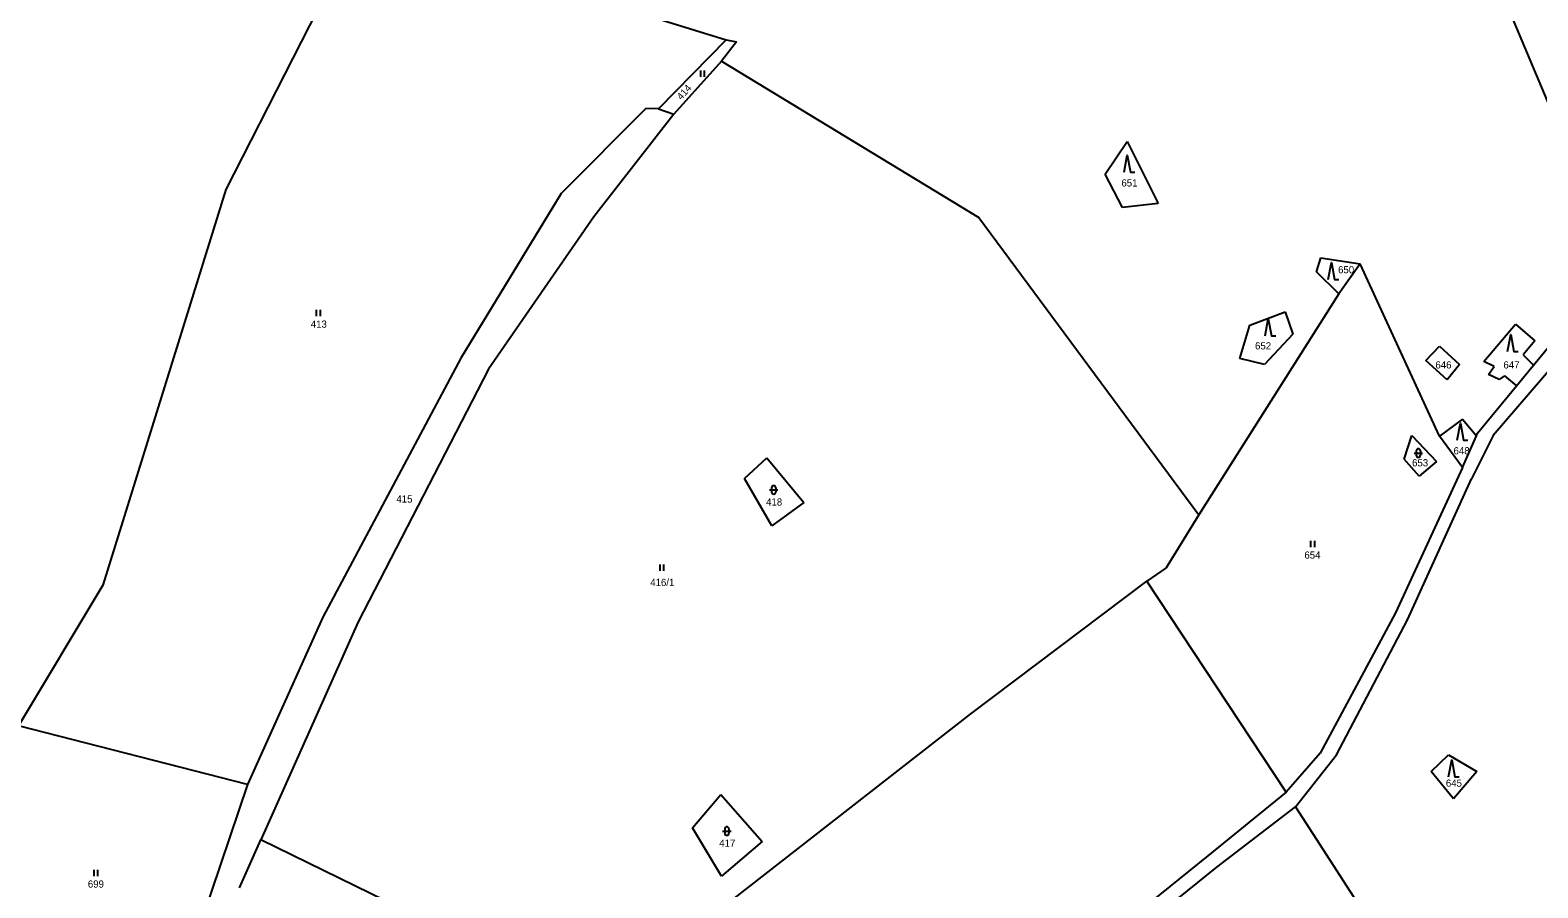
# Model space of a CAD drawing. Extents: x -670359 to -668019, y -978807 to -976674.
# Drawn here: x -668641.1 to -668285.6, y -977601.7 to -977399.4 of the extents above; entities that cross this region are included whole.
import ezdxf

# ---------------------------------------------------------------- set-up
doc = ezdxf.new("R2010")
doc.units = 0
for name, color, linetype in [('Hranice parcel', 7, 'Continuous'), ('Parcelní čísla', 7, 'Continuous'), ('Značky kultur', 7, 'Continuous')]:
    doc.layers.add(name, color=color, linetype=linetype)

msp = doc.modelspace()

# ---------------------------------------------------------------- linework, layer by layer
at = {"layer": 'Hranice parcel'}
msp.add_line((-668557.18, -977604.87), (-668586.71, -977590.44), dxfattribs=at)
for points in [[(-668280.24, -977423.45), (-668302.7, -977370)], [(-668563.4, -977375), (-668594.98, -977437.03)], [(-668563.4, -977375), (-668476.97, -977401.73)], [(-668476.97, -977401.73), (-668493, -977417.97)], [(-668476.97, -977401.73), (-668474.59, -977402.21)], [(-668474.59, -977402.21), (-668478.11, -977406.73)], [(-668478.11, -977406.73), (-668489.36, -977419.22)], [(-668478.11, -977406.73), (-668417.42, -977443.6)], [(-668495.96, -977417.94), (-668515.89, -977437.97)], [(-668489.36, -977419.22), (-668508.24, -977443.44)], [(-668493, -977417.97), (-668495.96, -977417.94)], [(-668493, -977417.97), (-668489.36, -977419.22)], [(-668387.59, -977433.44), (-668382.43, -977425.7)], [(-668382.43, -977425.7), (-668375.1, -977440.36)], [(-668383.54, -977441.27), (-668387.59, -977433.44)], [(-668594.98, -977437.03), (-668623.98, -977530.37)], [(-668515.89, -977437.97), (-668539.61, -977476.83)], [(-668375.1, -977440.36), (-668383.54, -977441.27)], [(-668508.24, -977443.44), (-668533.05, -977479.38)], [(-668417.42, -977443.6), (-668365.52, -977513.77)], [(-668337.79, -977456.48), (-668336.79, -977453.15)], [(-668336.79, -977453.15), (-668327.47, -977454.52)], [(-668327.47, -977454.52), (-668332.52, -977461.63)], [(-668308.8, -977495.19), (-668327.47, -977454.52)], [(-668332.52, -977461.63), (-668337.79, -977456.48)], [(-668332.52, -977461.63), (-668365.52, -977513.77)], [(-668353.53, -977469.05), (-668345.17, -977465.9)], [(-668345.17, -977465.9), (-668343.35, -977471.17)], [(-668269.51, -977464.09), (-668296.09, -977495.03)], [(-668286.58, -977478.47), (-668276.22, -977465.88)], [(-668355.89, -977476.89), (-668353.53, -977469.05)], [(-668298.33, -977477.63), (-668290.89, -977468.77)], [(-668290.89, -977468.77), (-668286.3, -977472.7)], [(-668343.35, -977471.17), (-668350.09, -977478.3)], [(-668286.3, -977472.7), (-668289.07, -977476.04)], [(-668312.02, -977477.39), (-668308.77, -977473.99)], [(-668308.77, -977473.99), (-668304.04, -977478.31)], [(-668289.07, -977476.04), (-668286.58, -977478.47)], [(-668539.61, -977476.83), (-668572.11, -977537.87)], [(-668533.05, -977479.38), (-668563.82, -977538.97)], [(-668350.09, -977478.3), (-668355.89, -977476.89)], [(-668306.97, -977481.89), (-668312.02, -977477.39)], [(-668304.04, -977478.31), (-668306.97, -977481.89)], [(-668295.9, -977478.81), (-668298.33, -977477.63)], [(-668297.2, -977480.68), (-668295.9, -977478.81)], [(-668290.59, -977483.34), (-668286.58, -977478.47)], [(-668299.79, -977494.52), (-668290.59, -977483.34)], [(-668294.72, -977481.84), (-668297.2, -977480.68)], [(-668293.49, -977481.01), (-668294.72, -977481.84)], [(-668293.49, -977481.01), (-668290.59, -977483.34)], [(-668303.38, -977491.22), (-668308.8, -977495.19)], [(-668303.38, -977491.22), (-668300.05, -977495.11)], [(-668300.05, -977495.11), (-668299.79, -977494.52)], [(-668317.08, -977500.66), (-668315.28, -977495.05)], [(-668315.28, -977495.05), (-668309.49, -977501.17)], [(-668303.38, -977502.59), (-668308.8, -977495.19)], [(-668303.38, -977502.59), (-668300.05, -977495.11)], [(-668296.09, -977495.03), (-668301.23, -977505.3)], [(-668472.69, -977505.2), (-668467.4, -977500.34)], [(-668467.4, -977500.34), (-668458.72, -977510.81)], [(-668313.54, -977504.63), (-668317.08, -977500.66)], [(-668309.49, -977501.17), (-668313.54, -977504.63)], [(-668466.2, -977516.39), (-668472.69, -977505.2)], [(-668303.38, -977502.59), (-668319.16, -977536.85)], [(-668316.34, -977538.55), (-668301.23, -977505.3)], [(-668458.72, -977510.81), (-668466.2, -977516.39)], [(-668365.52, -977513.77), (-668373.25, -977526.22)], [(-668373.25, -977526.22), (-668377.84, -977529.42)], [(-668419.28, -977560.69), (-668377.84, -977529.42)], [(-668344.92, -977579.16), (-668377.84, -977529.42)], [(-668623.98, -977530.37), (-668643.87, -977563.55)], [(-668319.16, -977536.85), (-668336.91, -977569.99)], [(-668572.11, -977537.87), (-668589.87, -977577.38)], [(-668563.82, -977538.97), (-668586.71, -977590.44)], [(-668333.08, -977570.37), (-668316.34, -977538.55)], [(-668508.63, -977630.34), (-668419.28, -977560.69)], [(-668589.87, -977577.38), (-668643.87, -977563.55)], [(-668336.91, -977569.99), (-668344.92, -977579.16)], [(-668342.72, -977582.59), (-668333.08, -977570.37)], [(-668310.71, -977574.28), (-668306.65, -977570.34)], [(-668306.65, -977570.34), (-668299.98, -977574.33)], [(-668305.49, -977580.78), (-668310.71, -977574.28)], [(-668299.98, -977574.33), (-668305.49, -977580.78)], [(-668589.87, -977577.38), (-668602.57, -977614.87)], [(-668484.97, -977587.6), (-668478.29, -977579.75)], [(-668478.29, -977579.75), (-668468.51, -977590.82)], [(-668344.92, -977579.16), (-668363.39, -977594.19)], [(-668361.32, -977596.83), (-668342.72, -977582.59)], [(-668342.72, -977582.59), (-668294.5, -977657.36)], [(-668591.75, -977601.77), (-668586.71, -977590.44)], [(-668478.08, -977598.96), (-668484.97, -977587.6)], [(-668468.51, -977590.82), (-668478.08, -977598.96)], [(-668363.39, -977594.19), (-668403.78, -977626.71)], [(-668402.04, -977629.73), (-668361.32, -977596.83)]]:
    msp.add_lwpolyline(points, dxfattribs=at)
at = {"layer": 'Značky kultur'}
for p, q in [((-668483.08, -977408.95), (-668483.08, -977410.45)), ((-668482.08, -977410.45), (-668482.08, -977408.95)), ((-668573.68, -977465.43), (-668573.68, -977466.93)), ((-668572.68, -977466.93), (-668572.68, -977465.43)), ((-668314.78, -977499.19), (-668312.78, -977499.19)), ((-668314.28, -977498.69), (-668314.28, -977499.69)), ((-668313.28, -977498.69), (-668313.28, -977499.69)), ((-668466.8, -977507.88), (-668464.8, -977507.88)), ((-668466.3, -977507.38), (-668466.3, -977508.38)), ((-668465.3, -977507.38), (-668465.3, -977508.38)), ((-668339.18, -977519.89), (-668339.18, -977521.39)), ((-668338.18, -977521.39), (-668338.18, -977519.89)), ((-668492.68, -977525.5), (-668492.68, -977527)), ((-668491.68, -977527), (-668491.68, -977525.5)), ((-668477.85, -977588.34), (-668475.85, -977588.34)), ((-668477.35, -977587.84), (-668477.35, -977588.84)), ((-668476.35, -977587.84), (-668476.35, -977588.84)), ((-668626.15, -977597.48), (-668626.15, -977598.98)), ((-668625.15, -977598.98), (-668625.15, -977597.48))]:
    msp.add_line(p, q, dxfattribs=at)
for points in [[(-668383.17, -977432.93), (-668382.42, -977428.93), (-668381.67, -977432.93), (-668380.67, -977432.93)], [(-668335.03, -977458.26), (-668334.28, -977454.26), (-668333.53, -977458.26), (-668332.53, -977458.26)], [(-668349.91, -977471.54), (-668349.16, -977467.54), (-668348.41, -977471.54), (-668347.41, -977471.54)], [(-668292.72, -977475.25), (-668291.97, -977471.25), (-668291.22, -977475.25), (-668290.22, -977475.25)], [(-668304.6, -977496.11), (-668303.85, -977492.11), (-668303.1, -977496.11), (-668302.1, -977496.11)], [(-668306.66, -977575.57), (-668305.91, -977571.57), (-668305.16, -977575.57), (-668304.16, -977575.57)]]:
    msp.add_lwpolyline(points, dxfattribs=at)
for centre, start, end in [((-668313.78, -977498.69), 0, 180), ((-668313.78, -977499.69), 180, 0), ((-668465.8, -977507.38), 0, 180), ((-668465.8, -977508.38), 180, 0), ((-668476.85, -977587.84), 0, 180), ((-668476.85, -977588.84), 180, 0)]:
    msp.add_arc(centre, 0.5, start, end, dxfattribs=at)

# ---------------------------------------------------------------- texts
at = {"layer": 'Parcelní čísla'}
msp.add_text('414', height=1.7, rotation=48.2606, dxfattribs=at).set_placement((-668487.57, -977416.03))
for s, p in [('651', (-668383.8, -977436.32)), ('650', (-668332.7, -977456.79)), ('413', (-668574.97, -977469.63)), ('652', (-668352.28, -977474.75)), ('646', (-668309.75, -977479.24)), ('647', (-668293.71, -977479.24)), ('648', (-668305.47, -977499.49)), ('653', (-668315.25, -977502.33)), ('415', (-668554.78, -977510.87)), ('418', (-668467.59, -977511.58)), ('654', (-668340.64, -977524.09)), ('416/1', (-668494.91, -977530.54)), ('645', (-668307.28, -977577.89)), ('417', (-668478.64, -977592.04)), ('699', (-668627.54, -977601.68))]:
    msp.add_text(s, height=1.7, dxfattribs=at).set_placement(p)

doc.saveas('drawing.dxf')
